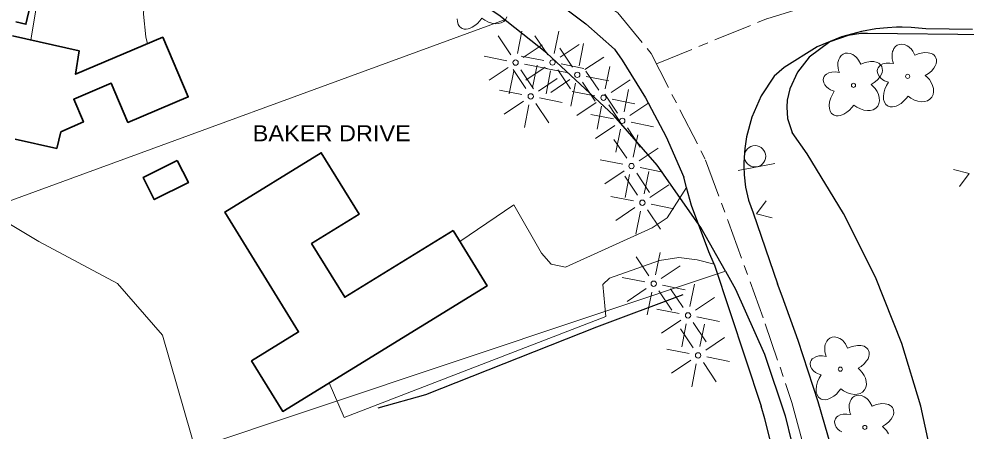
# Model space of a CAD drawing. Extents: x -861682 to -858969, y -1797841 to -1795153.
# Drawn here: x -859508.8 to -859153.4, y -1795912 to -1795757.2 of the extents above; entities that cross this region are included whole.
import ezdxf

# ---------------------------------------------------------------- set-up
doc = ezdxf.new("R2010")
doc.units = 0
doc.header["$LTSCALE"] = 2.4
doc.linetypes.add('LONG_DASH_SHORT_DASH', pattern=[9.9, 6, -1.2, 1.5, -1.2])
for name, color, linetype, lineweight in [('10', 7, 'Continuous', 25), ('11', 7, 'Continuous', 13), ('12', 7, 'Continuous', 35), ('14', 7, 'Continuous', 25), ('17', 7, 'Continuous', 13), ('18', 7, 'Continuous', 13), ('21', 7, 'Continuous', 13), ('30', 7, 'Continuous', 13), ('32', 7, 'LONG_DASH_SHORT_DASH', 13), ('37', 7, 'Continuous', 13), ('42', 7, 'Continuous', 25), ('46', 7, 'Continuous', 13)]:
    doc.layers.add(name, color=color, linetype=linetype, lineweight=lineweight)

msp = doc.modelspace()

# ---------------------------------------------------------------- linework, layer by layer
at = {"layer": '10'}
for p, q in [((-859151.007, -1795761.199), (-859168.553, -1795760.895)), ((-859258.276, -1795820.514), (-859259.316, -1795816.612)), ((-859247.886, -1795849.304), (-859230.246, -1795902.657))]:
    msp.add_line(p, q, dxfattribs=at)
for points in [[(-859346.563, -1795729.099), (-859341.946, -1795731.02), (-859322.267, -1795740.882), (-859309.217, -1795749.103), (-859296.016, -1795759.043), (-859285.303, -1795768.548)], [(-859168.553, -1795760.895), (-859174.04, -1795760.415), (-859177.345, -1795760.33), (-859179.548, -1795760.358), (-859182.85, -1795760.527), (-859187.233, -1795760.988), (-859192.658, -1795761.943), (-859200.096, -1795763.973), (-859209.264, -1795767.737), (-859221.596, -1795775.478), (-859225.429, -1795778.688)], [(-859285.303, -1795768.548), (-859282.47, -1795772.669), (-859273.66, -1795786.856), (-859265.962, -1795801.48), (-859259.316, -1795816.612)], [(-859225.429, -1795778.688), (-859230.23, -1795786.07), (-859233.778, -1795794.13), (-859235.78, -1795801.573), (-859236.444, -1795805.929), (-859236.71, -1795809.224), (-859236.776, -1795811.427), (-859236.775, -1795812.529), (-859236.64, -1795815.832), (-859236.107, -1795820.47), (-859235.099, -1795825.365)], [(-859247.886, -1795849.304), (-859249.977, -1795844.763), (-859256.479, -1795827.258), (-859258.276, -1795820.514)], [(-859235.099, -1795825.365), (-859233.299, -1795830.031), (-859224.152, -1795856.696)], [(-859195.488, -1795952.759), (-859198.204, -1795940.389), (-859202.803, -1795922.229), (-859208.876, -1795901.043), (-859216.374, -1795877.989), (-859222.374, -1795861.368), (-859224.152, -1795856.696)], [(-859214.603, -1795967.597), (-859215.462, -1795963.305), (-859220.98, -1795938.568), (-859228.914, -1795907.477), (-859230.246, -1795902.657)]]:
    msp.add_lwpolyline(points, dxfattribs=at)
at = {"layer": '11'}
for points in [[(-859504.257, -1795765.187), (-859500.241, -1795740.223), (-859481.007, -1795743.701), (-859478.748, -1795741.651), (-859456.627, -1795702.214), (-859456.367, -1795698.855), (-859458.783, -1795692.353)], [(-859460.559, -1795766.543), (-859461.108, -1795763.978), (-859462.029, -1795755.422), (-859461.475, -1795746.88), (-859458.155, -1795735.403), (-859453.997, -1795725.272), (-859446.843, -1795714.96), (-859438.175, -1795705.226), (-859431.584, -1795702.999), (-859427.7, -1795700.65)], [(-859343.36, -1795840.813), (-859323.076, -1795827.064), (-859312.721, -1795845.254), (-859309.055, -1795849.397), (-859303.668, -1795850.44), (-859271.207, -1795835.657), (-859265.587, -1795831.97), (-859258.276, -1795820.514)], [(-859392.331, -1795893.914), (-859386.769, -1795906.944), (-859288.556, -1795869.004), (-859289.633, -1795856.997), (-859287.176, -1795854.571), (-859268.389, -1795847.939), (-859261.16, -1795846.873), (-859254.319, -1795847.682), (-859247.886, -1795849.304)]]:
    msp.add_lwpolyline(points, dxfattribs=at)
at = {"layer": '12'}
for points in [[(-859504.592, -1795752.296), (-859506.14, -1795759.22), (-859509.983, -1795758.361)], [(-859511.164, -1795763.643), (-859486.235, -1795769.216), (-859487.488, -1795777.991), (-859454.789, -1795764.09), (-859445.26, -1795786.504), (-859467.871, -1795796.117), (-859474.127, -1795781.403), (-859488.235, -1795787.402), (-859484.605, -1795795.94), (-859493.036, -1795799.689), (-859494.581, -1795805.893), (-859510.21, -1795802.405)]]:
    msp.add_lwpolyline(points, dxfattribs=at)
for points in [[(-859345.855, -1795836.756), (-859386.556, -1795861.789), (-859398.981, -1795841.588), (-859381.137, -1795830.613), (-859395.337, -1795807.525), (-859431.548, -1795829.796), (-859403.856, -1795874.821), (-859421.466, -1795885.652), (-859409.782, -1795904.648), (-859333.105, -1795857.486)], [(-859449.352, -1795810.377), (-859462.152, -1795816.75), (-859458.002, -1795825.085), (-859445.202, -1795818.712)]]:
    msp.add_lwpolyline(points, close=True, dxfattribs=at)
at = {"layer": '14'}
msp.add_lwpolyline([(-859259.639, -1795860.87), (-859292.017, -1795872.952), (-859356.218, -1795898.481), (-859374.138, -1795903.44)], dxfattribs=at)
at = {"layer": '17'}
for p, q in [((-859321.758, -1795770.265), (-859320.032, -1795761.865)), ((-859307.912, -1795770.241), (-859306.186, -1795761.841)), ((-859324.218, -1795770.725), (-859329.008, -1795763.597)), ((-859310.372, -1795770.701), (-859315.162, -1795763.573)), ((-859298.617, -1795774.878), (-859296.891, -1795766.478)), ((-859319.558, -1795771.665), (-859312.462, -1795766.925)), ((-859301.077, -1795775.338), (-859305.867, -1795768.21)), ((-859305.712, -1795771.641), (-859298.616, -1795766.901)), ((-859325.718, -1795772.925), (-859334.18, -1795771.251)), ((-859311.872, -1795772.901), (-859320.334, -1795771.227)), ((-859296.417, -1795776.278), (-859289.321, -1795771.538)), ((-859325.178, -1795775.425), (-859332.404, -1795780.281)), ((-859324.798, -1795785.385), (-859323.118, -1795776.785)), ((-859318.541, -1795783.415), (-859323.331, -1795776.287)), ((-859320.458, -1795776.325), (-859315.658, -1795783.539)), ((-859319.118, -1795774.185), (-859310.638, -1795775.909)), ((-859311.332, -1795775.401), (-859318.558, -1795780.257)), ((-859316.081, -1795782.955), (-859314.355, -1795774.555)), ((-859302.577, -1795777.538), (-859311.039, -1795775.864)), ((-859310.952, -1795785.361), (-859309.272, -1795776.761)), ((-859306.612, -1795776.301), (-859301.812, -1795783.515)), ((-859305.272, -1795774.161), (-859296.792, -1795775.885)), ((-859291.234, -1795783.942), (-859296.024, -1795776.814)), ((-859288.774, -1795783.482), (-859287.048, -1795775.082)), ((-859313.881, -1795784.355), (-859306.785, -1795779.615)), ((-859302.037, -1795780.038), (-859309.263, -1795784.894)), ((-859295.977, -1795778.798), (-859287.497, -1795780.522)), ((-859286.574, -1795784.882), (-859279.478, -1795780.142)), ((-859320.041, -1795785.615), (-859328.503, -1795783.941)), ((-859301.657, -1795789.998), (-859299.977, -1795781.398)), ((-859297.317, -1795780.938), (-859292.517, -1795788.152)), ((-859281.744, -1795792.137), (-859280.018, -1795783.737)), ((-859313.441, -1795786.875), (-859304.961, -1795788.599)), ((-859292.734, -1795786.142), (-859301.196, -1795784.468)), ((-859284.204, -1795792.597), (-859288.994, -1795785.469)), ((-859286.134, -1795787.402), (-859277.654, -1795789.126)), ((-859319.501, -1795788.115), (-859326.727, -1795792.971)), ((-859319.121, -1795798.075), (-859317.441, -1795789.475)), ((-859314.781, -1795789.015), (-859309.981, -1795796.229)), ((-859292.194, -1795788.642), (-859299.42, -1795793.498)), ((-859291.814, -1795798.602), (-859290.134, -1795790.002)), ((-859287.474, -1795789.542), (-859282.674, -1795796.756)), ((-859279.544, -1795793.537), (-859272.448, -1795788.797)), ((-859285.704, -1795794.797), (-859294.166, -1795793.123)), ((-859285.164, -1795797.297), (-859292.39, -1795802.153)), ((-859280.444, -1795798.197), (-859275.644, -1795805.411)), ((-859279.104, -1795796.057), (-859270.624, -1795797.781)), ((-859284.784, -1795807.257), (-859283.104, -1795798.657)), ((-859278.279, -1795809.129), (-859276.553, -1795800.729)), ((-859280.739, -1795809.589), (-859285.529, -1795802.461)), ((-859276.079, -1795810.529), (-859268.983, -1795805.789)), ((-859282.239, -1795811.789), (-859290.701, -1795810.115)), ((-859281.699, -1795814.289), (-859288.925, -1795819.145)), ((-859276.671, -1795823.383), (-859281.461, -1795816.255)), ((-859281.319, -1795824.249), (-859279.639, -1795815.649)), ((-859276.979, -1795815.189), (-859272.179, -1795822.403)), ((-859275.639, -1795813.049), (-859267.159, -1795814.773)), ((-859274.211, -1795822.923), (-859272.485, -1795814.523)), ((-859272.011, -1795824.323), (-859264.915, -1795819.583)), ((-859278.171, -1795825.583), (-859286.633, -1795823.909)), ((-859271.571, -1795826.843), (-859263.091, -1795828.567)), ((-859277.631, -1795828.083), (-859284.857, -1795832.939)), ((-859277.251, -1795838.043), (-859275.571, -1795829.443)), ((-859272.911, -1795828.983), (-859268.111, -1795836.197)), ((-859272.418, -1795853.771), (-859277.208, -1795846.643)), ((-859269.958, -1795853.311), (-859268.232, -1795844.911)), ((-859267.758, -1795854.711), (-859260.662, -1795849.971)), ((-859273.918, -1795855.971), (-859282.38, -1795854.297)), ((-859273.378, -1795858.471), (-859280.604, -1795863.327)), ((-859267.318, -1795857.231), (-859258.838, -1795858.955)), ((-859259.529, -1795865.675), (-859264.319, -1795858.547)), ((-859257.069, -1795865.215), (-859255.343, -1795856.815)), ((-859272.998, -1795868.431), (-859271.318, -1795859.831)), ((-859268.658, -1795859.371), (-859263.858, -1795866.585)), ((-859254.869, -1795866.615), (-859247.773, -1795861.875)), ((-859261.029, -1795867.875), (-859269.491, -1795866.201)), ((-859254.429, -1795869.135), (-859245.949, -1795870.859)), ((-859260.489, -1795870.375), (-859267.715, -1795875.231)), ((-859260.109, -1795880.335), (-859258.429, -1795871.735)), ((-859255.769, -1795871.275), (-859250.969, -1795878.489)), ((-859253.283, -1795880.257), (-859251.557, -1795871.857)), ((-859255.743, -1795880.717), (-859260.533, -1795873.589)), ((-859251.083, -1795881.657), (-859243.987, -1795876.917)), ((-859257.243, -1795882.917), (-859265.705, -1795881.243)), ((-859256.703, -1795885.417), (-859263.929, -1795890.273)), ((-859256.323, -1795895.377), (-859254.643, -1795886.777)), ((-859251.983, -1795886.317), (-859247.183, -1795893.531)), ((-859250.643, -1795884.177), (-859242.163, -1795885.901))]:
    msp.add_line(p, q, dxfattribs=at)
for points in [[(-859344.292, -1795757.159), (-859344.282, -1795758.249), (-859343.948, -1795759.267), (-859343.426, -1795760.113), (-859342.868, -1795760.549), (-859342.482, -1795760.795), (-859341.748, -1795761.019), (-859340.954, -1795761.031), (-859340.184, -1795760.907), (-859339.524, -1795760.695), (-859338.78, -1795760.373), (-859337.704, -1795759.693), (-859336.742, -1795758.907), (-859335.786, -1795757.889), (-859335.04, -1795756.979)], [(-859335.044, -1795756.969), (-859334.002, -1795757.737), (-859332.596, -1795758.459), (-859331.348, -1795758.865), (-859329.976, -1795759.061), (-859328.958, -1795759.011), (-859327.814, -1795758.721), (-859326.882, -1795758.169), (-859326.142, -1795757.381), (-859325.674, -1795756.423)], [(-859195.473, -1795789.571), (-859194.431, -1795790.339), (-859193.025, -1795791.061), (-859191.777, -1795791.467), (-859190.405, -1795791.663), (-859189.387, -1795791.613), (-859188.243, -1795791.323), (-859187.311, -1795790.771), (-859186.571, -1795789.983), (-859186.103, -1795789.025), (-859185.893, -1795787.947), (-859185.997, -1795786.751), (-859186.287, -1795785.579), (-859186.773, -1795784.519), (-859187.495, -1795783.375), (-859188.361, -1795782.455), (-859189.043, -1795781.843), (-859187.861, -1795781.127), (-859186.715, -1795780.179), (-859185.795, -1795779.087), (-859185.273, -1795778.231), (-859184.941, -1795777.417), (-859184.795, -1795776.601), (-859184.835, -1795775.839), (-859185.051, -1795775.159), (-859185.309, -1795774.707), (-859185.729, -1795774.233), (-859186.189, -1795773.879), (-859186.755, -1795773.589), (-859187.991, -1795773.261), (-859189.233, -1795773.227), (-859191.279, -1795773.603), (-859192.939, -1795774.241), (-859193.729, -1795772.663), (-859194.383, -1795771.849), (-859194.795, -1795771.447), (-859195.259, -1795771.047), (-859195.861, -1795770.655), (-859196.865, -1795770.223), (-859197.879, -1795770.053), (-859198.767, -1795770.153), (-859199.567, -1795770.487), (-859200.233, -1795770.973), (-859200.793, -1795771.679), (-859201.143, -1795772.435), (-859201.301, -1795772.873), (-859201.469, -1795773.549), (-859201.521, -1795774.711), (-859201.449, -1795775.609), (-859201.237, -1795776.571), (-859200.953, -1795777.377), (-859202.395, -1795777.145), (-859203.753, -1795777.195), (-859204.911, -1795777.481), (-859205.799, -1795777.979), (-859206.239, -1795778.323), (-859206.673, -1795778.889), (-859206.911, -1795779.423), (-859207.035, -1795780.101), (-859206.833, -1795781.205), (-859206.377, -1795782.017), (-859205.753, -1795782.779), (-859204.975, -1795783.395), (-859204.277, -1795783.819), (-859203.613, -1795784.107), (-859202.885, -1795784.345), (-859203.569, -1795785.557), (-859204.191, -1795786.925), (-859204.587, -1795788.427), (-859204.721, -1795789.761), (-859204.711, -1795790.851), (-859204.377, -1795791.869), (-859203.855, -1795792.715), (-859203.297, -1795793.151), (-859202.911, -1795793.397), (-859202.177, -1795793.621), (-859201.383, -1795793.633), (-859200.613, -1795793.509), (-859199.953, -1795793.297), (-859199.209, -1795792.975), (-859198.133, -1795792.295), (-859197.171, -1795791.509), (-859196.215, -1795790.491), (-859195.469, -1795789.581)], [(-859175.15, -1795786.224), (-859174.108, -1795786.992), (-859172.702, -1795787.714), (-859171.454, -1795788.12), (-859170.082, -1795788.316), (-859169.064, -1795788.266), (-859167.92, -1795787.976), (-859166.988, -1795787.424), (-859166.248, -1795786.636), (-859165.78, -1795785.678), (-859165.57, -1795784.6), (-859165.674, -1795783.404), (-859165.964, -1795782.232), (-859166.45, -1795781.172), (-859167.172, -1795780.028), (-859168.038, -1795779.108), (-859168.72, -1795778.496), (-859167.538, -1795777.78), (-859166.392, -1795776.832), (-859165.472, -1795775.74), (-859164.95, -1795774.884), (-859164.618, -1795774.07), (-859164.472, -1795773.254), (-859164.512, -1795772.492), (-859164.728, -1795771.812), (-859164.986, -1795771.36), (-859165.406, -1795770.886), (-859165.866, -1795770.532), (-859166.432, -1795770.242), (-859167.668, -1795769.914), (-859168.91, -1795769.88), (-859170.956, -1795770.256), (-859172.616, -1795770.894), (-859173.406, -1795769.316), (-859174.06, -1795768.502), (-859174.472, -1795768.1), (-859174.936, -1795767.7), (-859175.538, -1795767.308), (-859176.542, -1795766.876), (-859177.556, -1795766.706), (-859178.444, -1795766.806), (-859179.244, -1795767.14), (-859179.91, -1795767.626), (-859180.47, -1795768.332), (-859180.82, -1795769.088), (-859180.978, -1795769.526), (-859181.146, -1795770.202), (-859181.198, -1795771.364), (-859181.126, -1795772.262), (-859180.914, -1795773.224), (-859180.63, -1795774.03), (-859182.072, -1795773.798), (-859183.43, -1795773.848), (-859184.588, -1795774.134), (-859185.476, -1795774.632), (-859185.916, -1795774.976), (-859186.35, -1795775.542), (-859186.588, -1795776.076), (-859186.712, -1795776.754), (-859186.51, -1795777.858), (-859186.054, -1795778.67), (-859185.43, -1795779.432), (-859184.652, -1795780.048), (-859183.954, -1795780.472), (-859183.29, -1795780.76), (-859182.562, -1795780.998), (-859183.246, -1795782.21), (-859183.868, -1795783.578), (-859184.264, -1795785.08), (-859184.398, -1795786.414), (-859184.388, -1795787.504), (-859184.054, -1795788.522), (-859183.532, -1795789.368), (-859182.974, -1795789.804), (-859182.588, -1795790.05), (-859181.854, -1795790.274), (-859181.06, -1795790.286), (-859180.29, -1795790.162), (-859179.63, -1795789.95), (-859178.886, -1795789.628), (-859177.81, -1795788.948), (-859176.848, -1795788.162), (-859175.892, -1795787.144), (-859175.146, -1795786.234)], [(-859200.385, -1795896.181), (-859199.343, -1795896.949), (-859197.937, -1795897.671), (-859196.689, -1795898.077), (-859195.317, -1795898.273), (-859194.299, -1795898.223), (-859193.155, -1795897.933), (-859192.223, -1795897.381), (-859191.483, -1795896.593), (-859191.015, -1795895.635), (-859190.805, -1795894.557), (-859190.909, -1795893.361), (-859191.199, -1795892.189), (-859191.685, -1795891.129), (-859192.407, -1795889.985), (-859193.273, -1795889.065), (-859193.955, -1795888.453), (-859192.773, -1795887.737), (-859191.627, -1795886.789), (-859190.707, -1795885.697), (-859190.185, -1795884.841), (-859189.853, -1795884.027), (-859189.707, -1795883.211), (-859189.747, -1795882.449), (-859189.963, -1795881.769), (-859190.221, -1795881.317), (-859190.641, -1795880.843), (-859191.101, -1795880.489), (-859191.667, -1795880.199), (-859192.903, -1795879.871), (-859194.145, -1795879.837), (-859196.191, -1795880.213), (-859197.851, -1795880.851), (-859198.641, -1795879.273), (-859199.295, -1795878.459), (-859199.707, -1795878.057), (-859200.171, -1795877.657), (-859200.773, -1795877.265), (-859201.777, -1795876.833), (-859202.791, -1795876.663), (-859203.679, -1795876.763), (-859204.479, -1795877.097), (-859205.145, -1795877.583), (-859205.705, -1795878.289), (-859206.055, -1795879.045), (-859206.213, -1795879.483), (-859206.381, -1795880.159), (-859206.433, -1795881.321), (-859206.361, -1795882.219), (-859206.149, -1795883.181), (-859205.865, -1795883.987), (-859207.307, -1795883.755), (-859208.665, -1795883.805), (-859209.823, -1795884.091), (-859210.711, -1795884.589), (-859211.151, -1795884.933), (-859211.585, -1795885.499), (-859211.823, -1795886.033), (-859211.947, -1795886.711), (-859211.745, -1795887.815), (-859211.289, -1795888.627), (-859210.665, -1795889.389), (-859209.887, -1795890.005), (-859209.189, -1795890.429), (-859208.525, -1795890.717), (-859207.797, -1795890.955), (-859208.481, -1795892.167), (-859209.103, -1795893.535), (-859209.499, -1795895.037), (-859209.633, -1795896.371), (-859209.623, -1795897.461), (-859209.289, -1795898.479), (-859208.767, -1795899.325), (-859208.209, -1795899.761), (-859207.823, -1795900.007), (-859207.089, -1795900.231), (-859206.295, -1795900.243), (-859205.525, -1795900.119), (-859204.865, -1795899.907), (-859204.121, -1795899.585), (-859203.045, -1795898.905), (-859202.083, -1795898.119), (-859201.127, -1795897.101), (-859200.381, -1795896.191)], [(-859182.523, -1795913.011), (-859183.245, -1795911.867), (-859184.111, -1795910.947), (-859184.793, -1795910.335), (-859183.611, -1795909.619), (-859182.465, -1795908.671), (-859181.545, -1795907.579), (-859181.023, -1795906.723), (-859180.691, -1795905.909), (-859180.545, -1795905.093), (-859180.585, -1795904.331), (-859180.801, -1795903.651), (-859181.059, -1795903.199), (-859181.479, -1795902.725), (-859181.939, -1795902.371), (-859182.505, -1795902.081), (-859183.741, -1795901.753), (-859184.983, -1795901.719), (-859187.029, -1795902.095), (-859188.689, -1795902.733), (-859189.479, -1795901.155), (-859190.133, -1795900.341), (-859190.545, -1795899.939), (-859191.009, -1795899.539), (-859191.611, -1795899.147), (-859192.615, -1795898.715), (-859193.629, -1795898.545), (-859194.517, -1795898.645), (-859195.317, -1795898.979), (-859195.983, -1795899.465), (-859196.543, -1795900.171), (-859196.893, -1795900.927), (-859197.051, -1795901.365), (-859197.219, -1795902.041), (-859197.271, -1795903.203), (-859197.199, -1795904.101), (-859196.987, -1795905.063), (-859196.703, -1795905.869), (-859198.145, -1795905.637), (-859199.503, -1795905.687), (-859200.661, -1795905.973), (-859201.549, -1795906.471), (-859201.989, -1795906.815), (-859202.423, -1795907.381), (-859202.661, -1795907.915), (-859202.785, -1795908.593), (-859202.583, -1795909.697), (-859202.127, -1795910.509), (-859201.503, -1795911.271), (-859200.725, -1795911.887), (-859200.027, -1795912.311)]]:
    msp.add_lwpolyline(points, dxfattribs=at)
for centre, radius in [((-859322.418, -1795773.625), 1), ((-859308.572, -1795773.601), 1), ((-859299.277, -1795778.238), 1), ((-859175.33, -1795778.812), 0.773), ((-859195.653, -1795782.159), 0.773), ((-859316.741, -1795786.315), 1), ((-859289.434, -1795786.842), 1), ((-859282.404, -1795795.497), 1), ((-859278.939, -1795812.489), 1), ((-859274.871, -1795826.283), 1), ((-859270.618, -1795856.671), 1), ((-859257.729, -1795868.575), 1), ((-859253.943, -1795883.617), 1), ((-859200.565, -1795888.769), 0.773), ((-859191.403, -1795910.651), 0.773)]:
    msp.add_circle(centre, radius, dxfattribs=at)
at = {"layer": '18'}
msp.add_lwpolyline([(-859627.919, -1795735.544), (-859627.176, -1795761.517), (-859594.459, -1795791.233), (-859555.341, -1795807.819), (-859531.043, -1795823.004), (-859501.341, -1795840.813), (-859471.841, -1795856.609), (-859454.844, -1795876.018), (-859441.296, -1795923.448), (-859437.847, -1795959.975), (-859434.854, -1796007.018), (-859435.886, -1796048.843), (-859444.576, -1796099.933), (-859436.676, -1796124.239), (-859404.307, -1796131.553), (-859372.521, -1796121.23), (-859347.215, -1796129.795), (-859321.586, -1796150.045)], dxfattribs=at)
at = {"layer": '21'}
msp.add_line((-859225.186, -1795811.566), (-859238.946, -1795814.169), dxfattribs=at)
msp.add_circle((-859232.569, -1795808.832), 4, dxfattribs=at)
at = {"layer": '30'}
for p, q in [((-859326.547, -1795757.57), (-859745.262, -1795910.868)), ((-859243.627, -1795852.034), (-859698.943, -1796004.025))]:
    msp.add_line(p, q, dxfattribs=at)
at = {"layer": '32'}
for points in [[(-859608.727, -1795645.905), (-859547.475, -1795663.972), (-859512.218, -1795672.548), (-859448.852, -1795685.888), (-859390.25, -1795702.087), (-859346.418, -1795718.286), (-859312.114, -1795735.914), (-859284.005, -1795754.971), (-859271.617, -1795770.217), (-859251.13, -1795810.238), (-859242.554, -1795833.584), (-859228.738, -1795871.699), (-859218.732, -1795901.238), (-859209.68, -1795935.065), (-859202.057, -1795970.321), (-859196.34, -1796004.625), (-859192.528, -1796042.264), (-859177.759, -1796158.991), (-859172.04, -1796220.929), (-859156.019, -1796407.84)], [(-859269.621, -1795774.116), (-859228.136, -1795757.194), (-859208.945, -1795751.33), (-859190.274, -1795750.512), (-859076.743, -1795752.396), (-859047.957, -1795755.062), (-859007.977, -1795752.929), (-858987.309, -1795749.224)]]:
    msp.add_lwpolyline(points, dxfattribs=at)
at = {"layer": '37'}
for points in [[(-859158.108, -1795813.825), (-859152.257, -1795815.348), (-859155.825, -1795820.23)], [(-859226.123, -1795831.938), (-859231.977, -1795830.426), (-859228.419, -1795825.537)]]:
    msp.add_lwpolyline(points, dxfattribs=at)
at = {"layer": '42'}
msp.add_line((-859089.56, -1795763.911), (-859190.421, -1795762.699), dxfattribs=at)
for points in [[(-859243.627, -1795852.034), (-859252.875, -1795835.558), (-859269.338, -1795812.162), (-859285.617, -1795793.451), (-859310.747, -1795770.037), (-859328.757, -1795755.826), (-859356.224, -1795737.37), (-859385.126, -1795721.567), (-859415.296, -1795708.481), (-859441.665, -1795699.566), (-859470.894, -1795692.189), (-859482.19, -1795690.004)], [(-859190.421, -1795762.699), (-859192.839, -1795762.73), (-859197.641, -1795763.399), (-859204.48, -1795765.869), (-859212.251, -1795771.56), (-859216.639, -1795777.169), (-859219.52, -1795783.447), (-859220.497, -1795787.791), (-859220.695, -1795790.418), (-859220.348, -1795794.691), (-859218.694, -1795799.83)], [(-859163.411, -1795940.033), (-859166.107, -1795922.354), (-859170.428, -1795902.707), (-859177.51, -1795879.161), (-859187.395, -1795854.239), (-859199.37, -1795830.349), (-859213.089, -1795807.924), (-859218.694, -1795799.83)], [(-859243.627, -1795852.034), (-859239.857, -1795858.703), (-859229.069, -1795883.11), (-859221.294, -1795906.355), (-859216.519, -1795925.851), (-859213.511, -1795943.448)]]:
    msp.add_lwpolyline(points, dxfattribs=at)

# ---------------------------------------------------------------- texts
at = {"layer": '46', "width": 1.1}
msp.add_text('BAKER DRIVE', height=6, dxfattribs=at).set_placement((-859421.075, -1795803.178))

doc.saveas('drawing.dxf')
